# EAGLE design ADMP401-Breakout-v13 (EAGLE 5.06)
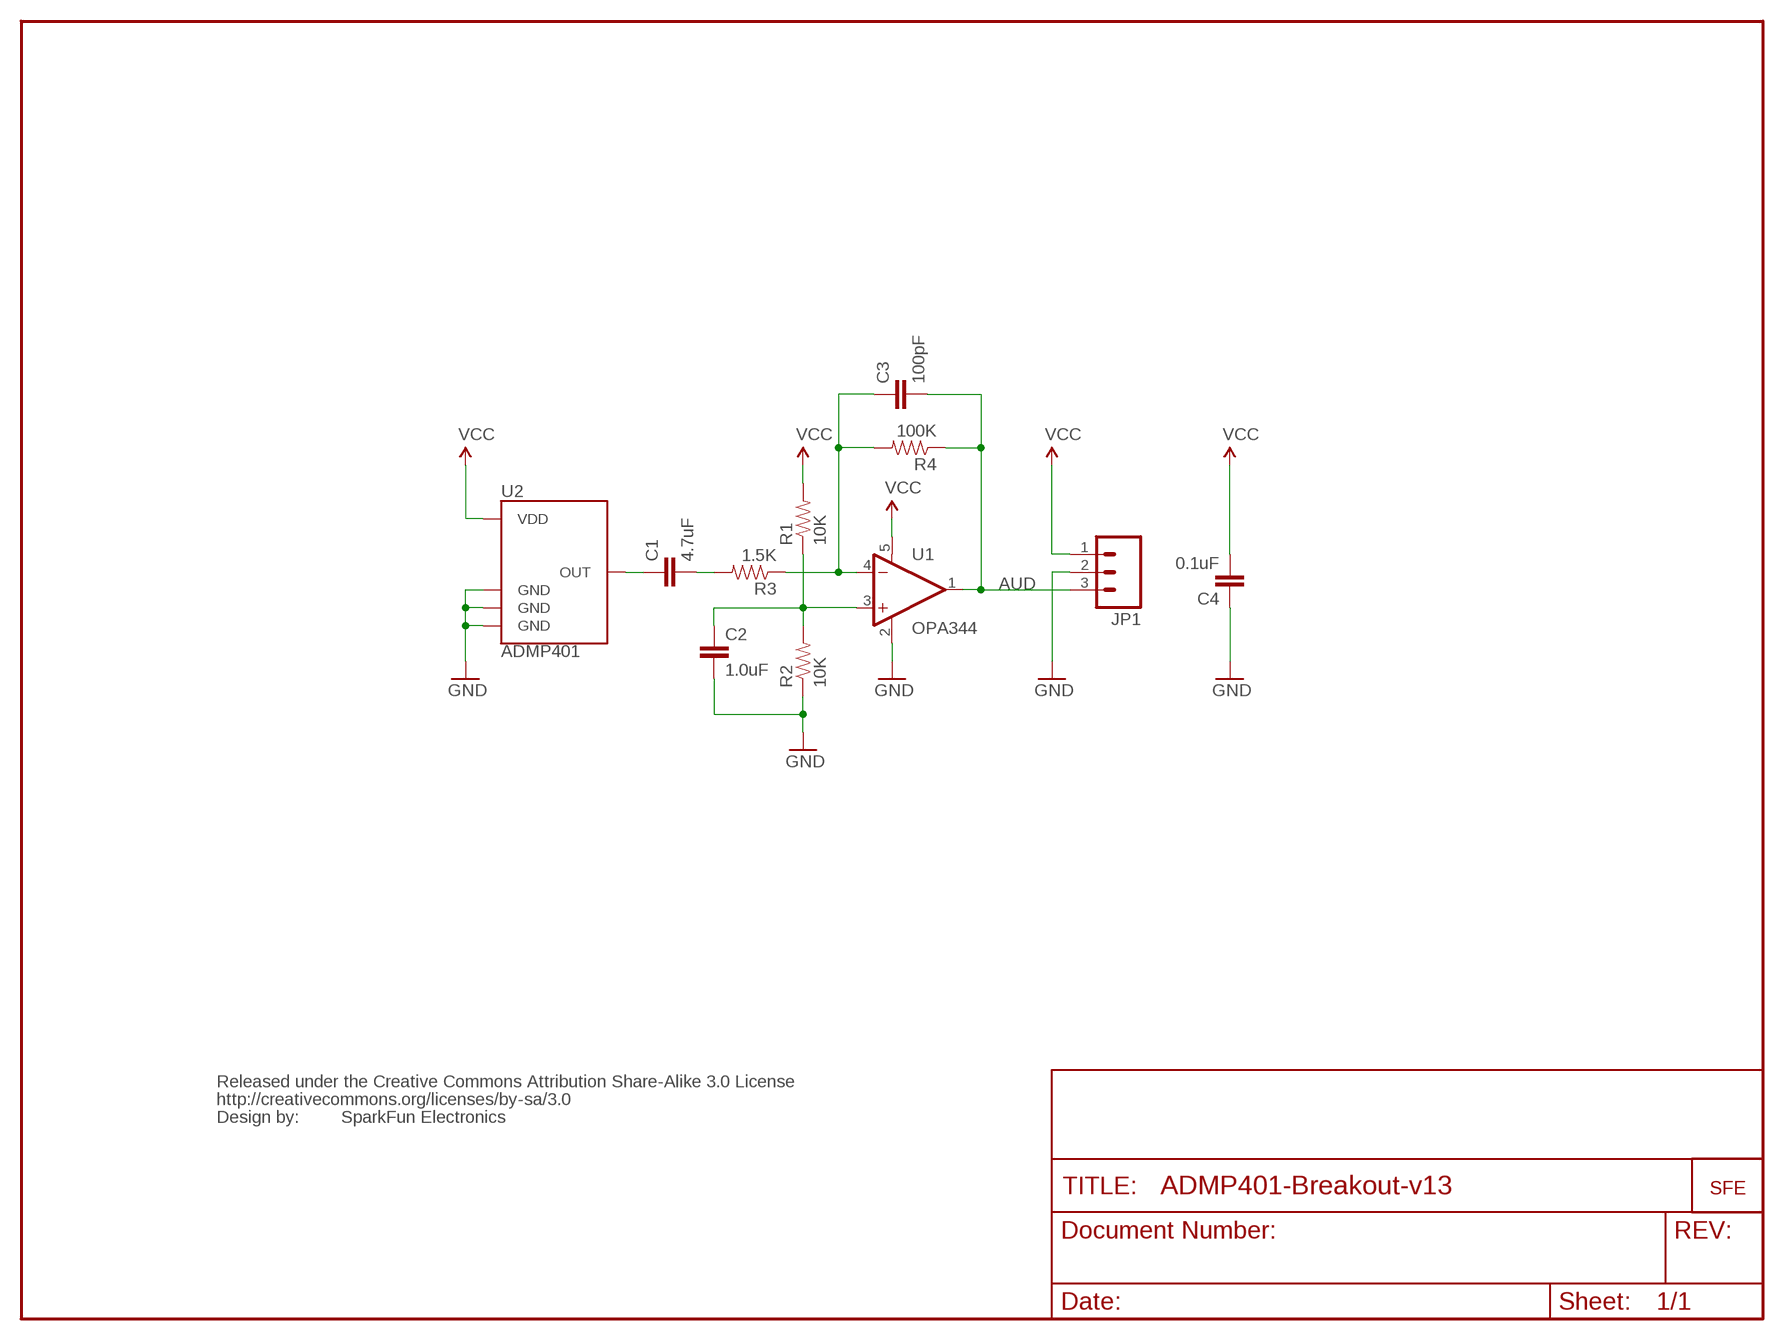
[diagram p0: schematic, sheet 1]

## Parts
C1  4.7uF  CAP0402-CAP  [0402-CAP]
C2  1.0uF  CAP0402-CAP  [0402-CAP]
C3  100pF  CAP0402-CAP  [0402-CAP]
C4  0.1uF  CAP0402-CAP  [0402-CAP]
JP1  M03PTH  [1X03]
R1  10K  RESISTOR0402-RES  [0402-RES]
R2  10K  RESISTOR0402-RES  [0402-RES]
R3  1.5K  RESISTOR0402-RES  [0402-RES]
R4  100K  RESISTOR0402-RES  [0402-RES]
U1  OPA344  [SOT23-5]
U2  ADMP401  [ADMP401]
U$1  LOGO-SFESK  [SFE-LOGO-FLAME]
U$2  CREATIVE_COMMONS  [CREATIVE_COMMONS]

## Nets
AUD: C3.2 JP1.3 R4.1 U1.1(OUT)
GND: C2.2 C4.1 JP1.2 R2.1 U1.2(V-) U2.2(GND) U2.4(GND) U2.6(GND)
N$1: C1.1 U2.1(OUT)
N$2: C3.1 R3.1 R4.2 U1.4(-IN)
N$6: C1.2 R3.2
N$7: C2.1 R1.1 R2.2 U1.3(+IN)
VCC: C4.2 JP1.1 R1.2 U1.5(V+) U2.5(VDD)

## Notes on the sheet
- SparkFun Electronics

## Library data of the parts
C1-C4 = SparkFun:CAP: Capacitor
JP1 = SparkFun:M03: Header 3 Standard 3-pin 0.1" header. Use with straight break away headers (SKU : PRT-00116), right angle break away headers (PRT-00553), swiss pins (PRT-00743), machine pins (PRT-00117), and female headers (PRT-00115). Molex polarized connector foot print use with SKU : PRT-08232 with associated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
R1-R4 = SparkFun:RESISTOR: Resistor
U1 = SparkFun:OPA344
U2 = SparkFun:ADMP401
U$1 = SparkFun:LOGO-SFE: Spark Fun Electronics PCB Logo
U$2 = SparkFun:CREATIVE_COMMONS

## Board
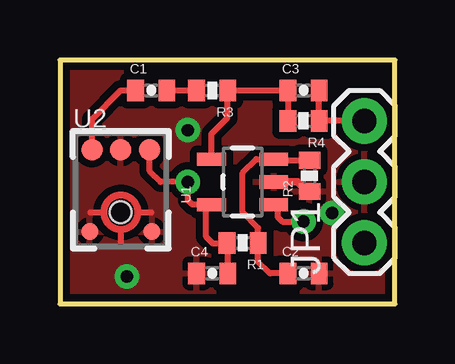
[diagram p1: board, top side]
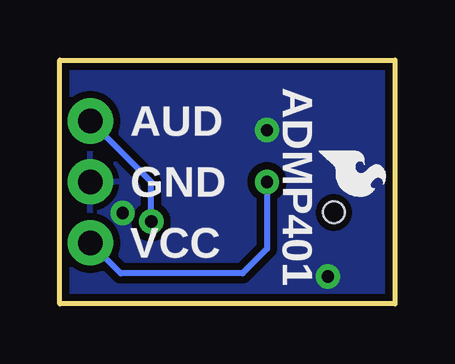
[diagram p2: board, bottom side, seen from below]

Size 13.97 x 10.16 mm. Coordinates in mm from the lower left corner, seen from the top.
Outline: 0,0 13.97,0 13.97,10.16 0,10.16 0,0
Copper layers (1*16): Top 0.035mm / dielectric 1.5mm / Bottom 0.035mm
Design rules "SparkFun": minimum track width 8mil, minimum drill 20mil, track to track 8mil, track to pad 8mil, pad to pad 8mil, via to via 8mil, smd to smd 8mil, copper to edge 9mil, drill to drill 8mil, minimum pad ring 12mil, minimum via ring 10mil, stop-mask expansion 4mil, vias tented up to drill 20mil, thermal gap 10mil

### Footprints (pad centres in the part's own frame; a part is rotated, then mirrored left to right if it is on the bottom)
0402-CAP = smd 0.7 x 0.9: 1 -0.65,0; 2 0.65,0
1X03 = drill 1.016 pad 1.88 round: 1 0,0; 2 2.54,0; 3 5.08,0
0402-RES = smd 0.7 x 0.9: 1 -0.65,0; 2 0.65,0
SOT23-5 = smd 0.55 x 1.2: 1 -0.95,-1.3; 2 0,-1.3; 3 0.95,-1.3; 4 0.95,1.3; 5 -0.95,1.3
ADMP401 = smd 0.9 x 0.9: 1 -1.2,2.62; 5 1.2,2.62; 6 0,2.62 | smd 0.7 x 0.7: 2 1.3,-0.8; 4 -1.3,-0.8 | hole 0.9: 0,0

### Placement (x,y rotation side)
C1  3.81,8.89 0 top
C2  10.16,1.27 0 top
C3  10.16,8.89 0 top
C4  6.35,1.27 0 top
JP1  12.7,2.54 90 top
R1  7.62,2.54 180 top
R2  10.41,5.33 90 top
R3  6.35,8.89 180 top
R4  10.16,7.62 180 top
U1  7.62,5.08 90 top
U2  2.54,3.81 0 top
U$1  3.17,6.35 270 bottom
U$2  not placed on the board

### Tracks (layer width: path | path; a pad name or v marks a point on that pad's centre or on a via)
AUD  (via drill 0.51)
  Top 0.254: C3.2 R4.1 JP1.3 | U1.1 9.08,4.13 9.08,3.62 9.27,3.43 v10.16,3.43
  Bottom 0.254: v10.16,3.43 10.16,5.08 JP1.3
GND  (via drill 0.51)
  Top 0.254: 2.54,3 2.54,2.54 | 1.27,3.81 1.73,3.81 | 3.35,3.81 3.81,3.81
  Top 0.305: U1.2 9.91,5.08 10.3,4.68 R2.1
  other vias: 11.35,3.78 2.79,1.14 5.33,7.24
  pour Bottom (isolate 0.305): 0,0 0,10.16 13.97,10.16 13.97,0
  pour Top (isolate 0.305): 0,0 0,10.16 13.97,10.16 13.97,0
N$1
  Top 0.254: C1.1 2.54,8.89 1.34,7.69 U2.1
N$2
  Top 0.254: R3.1 C3.1 | R3.1 C3.1 | C3.1 R4.2 | U1.4 6.32,7.08 6.99,7.75 6.99,8.88 R3.1
N$6
  Top 0.254: C1.2 R3.2
N$7
  Top 0.254: R2.2 8.97,5.98 U1.3 | U1.3 8.89,6.06 | U1.3 8.19,6.03 7.62,5.46 7.62,3.81 8.27,3.16 R1.1 8.27,1.76 8.76,1.27 C2.1
VCC  (via drill 0.51)
  Top 0.254: C4.2 7,2.51 | 7,2.51 R1.2 | 7,2.51 6.38,2.51 6.1,2.79 6.1,3.91 U1.5 5.52,4.13 5.33,4.32 v5.33,5.08 4.19,5.08 3.74,5.53 U2.5
  Bottom 0.254: JP1.1 11.43,1.27 6.35,1.27 5.33,2.29 v5.33,5.08

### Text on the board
bPlace: ADMP401 | AUD | GND | VCC
tValues: DNP | Mic Breakout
